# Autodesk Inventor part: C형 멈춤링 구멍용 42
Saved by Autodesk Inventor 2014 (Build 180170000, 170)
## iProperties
Created: 2026-04
Part Number: C형 멈춤링 구멍용 42
Material: 일반
Document SubType Name: Modeling
Designer: dg
Density: 1 g/cm^3
Appearance: 기본값
Author: dg
Author: jhkim
Description: 리테이닝 링(C형)
Creation Date: 2026-03-27
Sending System: Autodesk Inventor 2026
Preprocessor: ST-DEVELOPER v20.1
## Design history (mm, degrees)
node "C형 멈춤링 구멍용 421"
body "Solid1"
node "기준1"
